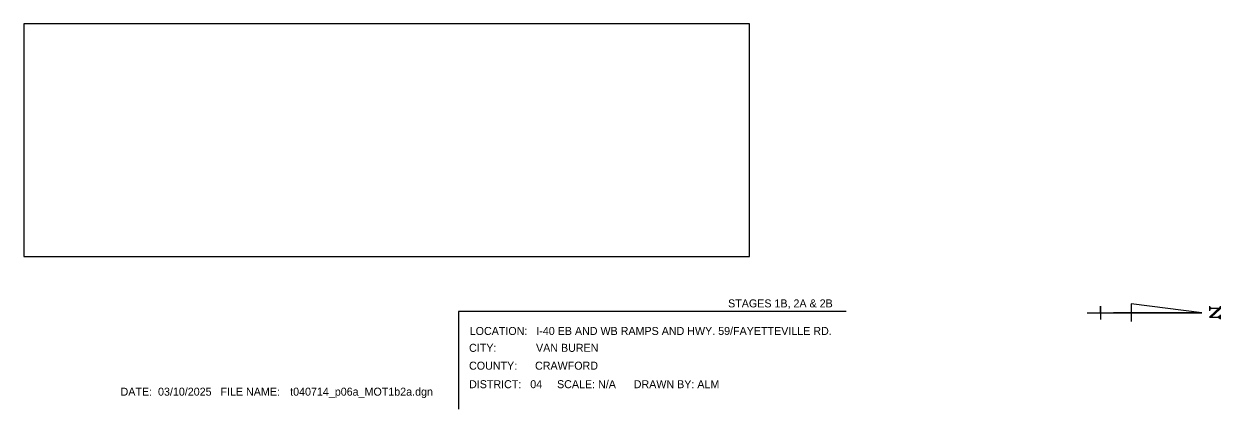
# Model space of a CAD drawing. Extents: x -218554 to 420030, y -566264 to -483460.
# Drawn here: x 419402 to 420030, y -565899 to -565697 of the extents above; entities that cross this region are included whole.
import ezdxf

# ---------------------------------------------------------------- set-up
doc = ezdxf.new("R2010")
doc.units = 0
for name, color, linetype in [('G-ANNO-STMP', 7, 'Continuous'), ('Level 1', 7, 'Continuous'), ('Level 10', 7, 'Continuous'), ('Level 57', 7, 'Continuous'), ('No Plot', 7, 'Continuous')]:
    doc.layers.add(name, color=color, linetype=linetype)

msp = doc.modelspace()

# ---------------------------------------------------------------- linework, layer by layer
at = {"layer": 'Level 1'}
for p, q in [((419983.8, -565843.6), (419983.79, -565852.87)), ((420020.9, -565848.24), (419983.8, -565843.6)), ((419960.61, -565848.23), (420020.9, -565848.24)), ((419960.61, -565848.23), (419974.52, -565848.23)), ((419960.61, -565848.23), (419967.56, -565848.23)), ((419967.56, -565848.23), (419967.56, -565844.75)), ((419967.56, -565844.75), (419967.56, -565851.71)), ((420020.9, -565848.24), (419974.52, -565848.23))]:
    msp.add_line(p, q, dxfattribs=at)
for points in [[(420024.77, -565844.84), (420024.77, -565847.25)], [(420030.4, -565845.28), (420024.77, -565850.54), (420029.45, -565850.54), (420030.39, -565851.2)], [(420029.66, -565845.94), (420025.72, -565845.94), (420024.77, -565845.28)], [(420025.72, -565845.94), (420024.77, -565846.23)], [(420024.77, -565846.38), (420025.72, -565845.94), (420024.77, -565846.52)], [(420030.4, -565845.79), (420025.28, -565850.54)], [(420030.4, -565846.01), (420025.58, -565850.54)], [(420030.4, -565844.84), (420030.4, -565846.23), (420025.72, -565850.54)], [(420030.4, -565849.88), (420029.45, -565850.54), (420030.4, -565850.83)], [(420029.45, -565850.54), (420030.39, -565850.98)], [(420030.39, -565849.23), (420030.4, -565851.64)]]:
    msp.add_lwpolyline(points, dxfattribs=at)
at = {"layer": 'Level 57'}
for points in [[(419630.59, -565847.55), (419630.59, -565898.75)], [(419834.17, -565847.55), (419630.59, -565847.55)]]:
    msp.add_lwpolyline(points, dxfattribs=at)
at = {"layer": 'No Plot'}
msp.add_lwpolyline([(419402.46, -565818.74), (419783.36, -565818.74), (419783.36, -565696.68), (419402.46, -565696.68)], close=True, dxfattribs=at)

# ---------------------------------------------------------------- texts
at = {"layer": 'G-ANNO-STMP'}
msp.add_text('STAGES 1B, 2A & 2B', height=4.2, dxfattribs=at).set_placement((419772.12, -565845.41))
at = {"layer": 'Level 10'}
for s, p in [('LOCATION:   I-40 EB AND WB RAMPS AND HWY. 59/FAYETTEVILLE RD.', (419636.48, -565859.87)), ('CITY:  ', (419636.14, -565868.72)), (' VAN BUREN', (419669.74, -565868.72)), ('COUNTY:      CRAWFORD', (419636.14, -565878.09)), ('DATE:  03/10/2025   FILE NAME: ', (419453.2, -565891.73)), ('t040714_p06a_MOT1b2a.dgn', (419542.23, -565891.73)), ('DISTRICT:   04     SCALE: N/A      DRAWN BY: ALM', (419636.14, -565887.81))]:
    msp.add_text(s, height=4.2, rotation=360, dxfattribs=at).set_placement(p)

doc.saveas('drawing.dxf')
